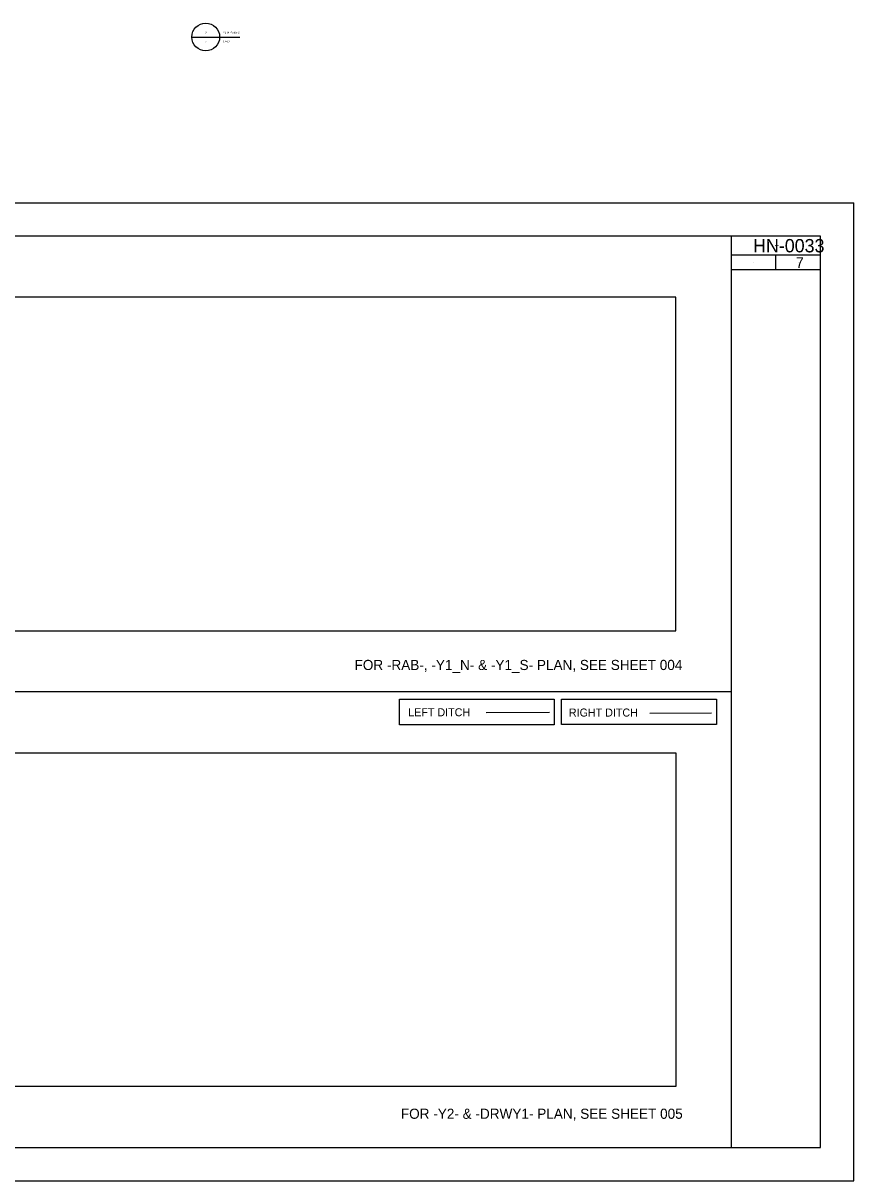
# Model space of a CAD drawing. Extents: x -1.87 to 4.42, y -0.33 to 2.17.
# Drawn here: x 1.277 to 2.833, y 0 to 2.17 of the extents above; entities that cross this region are included whole.
import ezdxf

# ---------------------------------------------------------------- set-up
doc = ezdxf.new("R2010")
doc.units = 0
for name, color, linetype in [('_CIVIL_CONSTRUCTION', 7, 'Continuous'), ('Default', 7, 'Continuous'), ('P_NCDOT_Vertical_Profile_Grade_Curve_Data_Label', 7, 'Continuous'), ('P_NCDOT_Vertical_Profile_Grade_Sheet_Elevation_Label', 7, 'Continuous'), ('P_NCDOT_Vertical_Profile_Grade_Sheet_Grid_Border', 7, 'Continuous'), ('P_NCDOT_Vertical_Profile_Grade_Sheet_Station_Label', 7, 'Continuous'), ('Sheet_Grid_Middle', 7, 'Continuous'), ('Sheet_Grid_Minor', 7, 'Continuous')]:
    doc.layers.add(name, color=color, linetype=linetype)

msp = doc.modelspace()

# ---------------------------------------------------------------- linework, layer by layer
at = {"layer": '_CIVIL_CONSTRUCTION'}
for p, q in [((2.1448, 0.8781), (2.2632, 0.8788)), ((2.4511, 0.8767), (2.5666, 0.877))]:
    msp.add_line(p, q, dxfattribs=at)
at = {"layer": 'Default'}
for p, q in [((1.5932, 2.144), (1.6453, 2.144)), ((1.6195, 2.144), (1.683, 2.144))]:
    msp.add_line(p, q, dxfattribs=at)
msp.add_circle((1.6192, 2.144), 0.026, dxfattribs=at)
at = {"layer": 'P_NCDOT_Vertical_Profile_Grade_Sheet_Elevation_Label'}
for points in [[(1.982, 0.903), (2.272, 0.903), (2.272, 0.8547), (1.982, 0.8547)], [(2.2856, 0.9031), (2.576, 0.9031), (2.576, 0.8554), (2.2856, 0.8554)]]:
    msp.add_lwpolyline(points, close=True, dxfattribs=at)
at = {"layer": 'P_NCDOT_Vertical_Profile_Grade_Sheet_Grid_Border'}
for centre in [(2.6908, 1.7529), (2.729, 1.7213)]:
    msp.add_circle(centre, 0.0001, dxfattribs=at)
at = {"layer": 'P_NCDOT_Vertical_Profile_Grade_Sheet_Station_Label'}
msp.add_line((1.6667, 1.0312), (1.8333, 1.0312), dxfattribs=at)
at = {"layer": 'Sheet_Grid_Middle'}
for p, q in [((2.7708, 1.7708), (0.0625, 1.7708)), ((2.6041, 0.0625), (2.6042, 1.7708)), ((2.7708, 0.0625), (2.7708, 1.7708)), ((2.7708, 1.7351), (2.6042, 1.7351)), ((2.6875, 1.7076), (2.6875, 1.7351)), ((2.7708, 1.7076), (2.6042, 1.7076)), ((2.6041, 0.9167), (0.0625, 0.9167)), ((0.0625, 0.0625), (2.7708, 0.0625))]:
    msp.add_line(p, q, dxfattribs=at)
msp.add_circle((2.6042, 1.7076), 0.0001, dxfattribs=at)
at = {"layer": 'Sheet_Grid_Minor'}
for p, q in [((0, 1.8333), (2.8333, 1.8333)), ((2.8333, 0), (2.8333, 1.8333)), ((0, 0), (2.8333, 0))]:
    msp.add_line(p, q, dxfattribs=at)
for points in [[(0.1667, 1.0312), (2.5, 1.0312), (2.5, 1.6562), (0.1667, 1.6562)], [(0.1666, 0.8021), (2.5, 0.8021), (2.5, 0.1771), (0.1666, 0.1771)]]:
    msp.add_lwpolyline(points, close=True, dxfattribs=at)
for centre in [(2.6875, 1.753), (2.6458, 1.7214), (2.7292, 1.7214)]:
    msp.add_circle(centre, 0.0001, dxfattribs=at)

# ---------------------------------------------------------------- texts
at = {"layer": '_CIVIL_CONSTRUCTION'}
for s, p in [('LEFT DITCH', (1.9986, 0.8708)), ('RIGHT DITCH', (2.2995, 0.8703))]:
    msp.add_text(s, height=0.015, dxfattribs=at).set_placement(p)
at = {"layer": 'Default'}
for s, height, p in [('3', 0.00328, (1.6181, 2.1506)), ('Y1_N -Profile 2', 0.003281, (1.6518, 2.1506)), ('7', 0.00328, (1.6183, 2.1342)), ('1"=50\'', 0.00328, (1.6518, 2.1342))]:
    msp.add_text(s, height=height, dxfattribs=at).set_placement(p)
at = {"layer": 'P_NCDOT_Vertical_Profile_Grade_Curve_Data_Label'}
for s, p in [('FOR -RAB-, -Y1_N- & -Y1_S- PLAN, SEE SHEET 004', (1.8979, 0.9575)), ('FOR -Y2- & -DRWY1- PLAN, SEE SHEET 005', (1.9847, 0.1163))]:
    msp.add_text(s, height=0.019, dxfattribs=at).set_placement(p)
at = {"layer": 'P_NCDOT_Vertical_Profile_Grade_Sheet_Grid_Border'}
for s, height, p in [('HN-0033', 0.025, (2.6445, 1.7404)), ('7', 0.02, (2.7247, 1.7113))]:
    msp.add_text(s, height=height, dxfattribs=at).set_placement(p)

doc.saveas('drawing.dxf')
